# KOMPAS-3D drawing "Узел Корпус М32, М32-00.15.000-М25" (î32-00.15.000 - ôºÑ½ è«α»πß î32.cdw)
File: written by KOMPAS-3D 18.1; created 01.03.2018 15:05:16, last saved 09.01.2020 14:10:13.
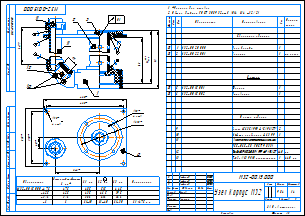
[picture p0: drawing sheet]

Sheet 1: A3, landscape

Document properties: Масса: 9.83678; Полное имя файла: М32-00.15.000 - Узел Корпус М32.a3d

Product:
- Part/product: Узел Корпус М32  | designation М32-00.15.000-М25  | pos. 0
    Масса: 9.06193
    Раздел спецификации: Сборочные единицы
    Форматы листов документа: A3
  - Component [detail]: Колено 90 @2~63 ф.FV Plast  | pos. 9  | Масса: 0.37; Раздел спецификации: Прочие изделия; source file: ..\..\..\..\1 ПКИ 3D\Полипропиленовые фитинги, трубы\Колено 90 ф63 ф.FV Plast.m3d
  - Component [detail]: Фланец  | designation М32-00.15.001  | pos. 5  | Материал: Полипропилен  ГОСТ 26996-86 (density 900 kg/m3); Масса: 0.816359; Раздел спецификации: Детали; Форматы листов документа: A3; source file: М32-00.15.001 - Фланец.m3d
  - Component [assembly]: Корпус  | designation М32-00.20.000  | pos. 1  | Материал: Полипропилен  ГОСТ 26996-86 (density 900 kg/m3); Масса: 2.99454; Раздел спецификации: Сборочные единицы; Форматы листов документа: A3; source file: ..\М32-00.20.000 - Корпус.a3d, ..\М32-00.20.000 - Корпус.cdw
  - Component [assembly]: Колонна  | designation М32-00.22.000  | pos. 2  | Масса: 0.990487; Раздел спецификации: Сборочные единицы; Форматы листов документа: A3; Примечание: см. заказ; source file: М32-00.22.000 - Колонна.a3d, М32-00.22.000 - Колонна.cdw
  - Component [detail]: Труба 63 PN10 S=5,8 FV PPR ф. FV PLAST  | pos. 11  | Материал: Полипропилен  ГОСТ 26996-86 (density 900 kg/m3); Масса: 0.152669; Раздел спецификации: Прочие изделия; Примечание: мм
  - Component [detail]: Основание  | designation М32-00.15.002-М25  | pos. 6  | Материал: Полипропилен  ГОСТ 26996-86 (density 900 kg/m3); Масса: 1.82071; Раздел спецификации: Детали; Форматы листов документа: A3
  - Component [assembly]: Муфта разборная ф63 РР  | pos. 10  | Масса: 1.69089; Раздел спецификации: Прочие изделия
- Part/product: Узел Корпус М32  | designation М32-00.15.000  | pos. 0
    Масса: 9.83678
    Раздел спецификации: Сборочные единицы
    Форматы листов документа: A3
    source file: М32-00.15.000 - Корпус М32.cdw
  - Component: Труба @2~63 PN10 полипропилен  | pos. 13  | Раздел спецификации: Прочие изделия; Примечание: 440 мм
  - Component [assembly]: Муфта разборная ф63 РР  | pos. 10  | Масса: 1.69089; Раздел спецификации: Прочие изделия; Зона: 2A
  - Component [detail]: Основание  | designation М32-00.15.002  | pos. 6
      Материал: Полипропилен  ГОСТ 26996-86 (density 900 kg/m3)
      Масса: 2.27958
      Раздел спецификации: Детали
      Форматы листов документа: A3
      Зона: 2A
      source file: М32-00.15.002 - Основание.cdw, М32-00.15.002 - Основание.m3d, М32-00.15.002-М25 - Основание.cdw
  - Component [detail]: Колено 45 63 FV PPR ф. "FV PLAST"  | pos. 9  | Материал: Полипропилен  ГОСТ 26996-86 (density 900 kg/m3); Масса: 0.34448; Раздел спецификации: Прочие изделия
  - Component [detail]: Труба 63 PN10 S=5,8 FV PPR ф. FV PLAST  | pos. 14  | Материал: Полипропилен  ГОСТ 26996-86; Масса: 0.0514; Раздел спецификации: Прочие изделия; Примечание: м
  - Component [detail]: Колено 45 63 FV PPR ф. "FV PLAST"  | pos. 9  | Материал: Полипропилен  ГОСТ 26996-86 (density 900 kg/m3); Масса: 0.34448; Раздел спецификации: Прочие изделия; Зона: 2A
  - Component [detail]: Труба 63 PN10 S=5,8 FV PPR ф. FV PLAST  | pos. 12  | Материал: Полипропилен  ГОСТ 26996-86 (density 900 kg/m3); Масса: 0.294541; Раздел спецификации: Прочие изделия; Примечание: мм; Зона: 2A
  - Component [detail]: Колонна  | designation М32-00.22.001  | pos. 2
      Масса: 0.990487
      Раздел спецификации: Сборочные единицы
      Форматы листов документа: A3
      Примечание: см. заказ
      Зона: 2A
      source file: М32-00.22.000 - Колонна.cdw, М32-00.22.001 - Колонна.m3d
  - Component [assembly]: Узел Корпус  | designation М32-00.20.000  | pos. 1
      Материал: Полипропилен  ГОСТ 26996-86 (density 900 kg/m3)
      Масса: 2.99454
      Раздел спецификации: Сборочные единицы
      Форматы листов документа: A3
      Зона: 2A
      source file: М32-00.20.000 - Корпус.cdw, М32-00.20.000 - Узел Корпус.a3d
  - Component [detail]: Фланец  | designation М32-00.15.001  | pos. 5
      Материал: Полипропилен  ГОСТ 26996-86 (density 900 kg/m3)
      Масса: 0.816359
      Раздел спецификации: Детали
      Форматы листов документа: A3
      Зона: 2A
      source file: М32-00.15.001 - Фланец.cdw, М32-00.15.001 - Фланец.m3d
  - Component: (в комплекте с уплотнительным кольцом / 055-065-58 ГОСТ 9833)  | pos. 11  | Раздел спецификации: Прочие изделия
- Part/product: Корпус М32 с косячным корпусом М40  | designation М32-00.15.000-666  | pos. 0
    Масса: 9.75067
    Раздел спецификации: Сборочные единицы
    Форматы листов документа: A3
  - Component [detail]: Труба 63 PN10 S=5,8 FV PPR ф. FV PLAST  | designation 1001  | pos. 11  | Материал: Полипропилен  ГОСТ 26996-86 (density 900 kg/m3); Масса: 0.324558; Раздел спецификации: Прочие изделия; Примечание: мм
  - Component [detail]: Колено 45@1~ @2~63 FV PPR ф. "FV PLAST"  | qty 2  | pos. 10  | Материал: Полипропилен  ГОСТ 26996-86 (density 900 kg/m3); Масса: 0.34448; Раздел спецификации: Прочие изделия
  - Component [detail]: Труба 63 PN10 S=5,8 FV PPR ф. FV PLAST  | designation М32колено  | pos. 0  | Материал: Полипропилен  ГОСТ 26996-86 (density 900 kg/m3); Масса: 0.051404; Раздел спецификации: Прочие изделия; Примечание: м
  - Component [assembly]: Муфта разборная ф63 РР  | pos. 11  | Масса: 1.69089; Раздел спецификации: Прочие изделия
  - Component [assembly]: Корпус косячный ММ32  | designation М40-00.30.000-666  | pos. 17  | Материал: Полипропилен  ГОСТ 26996-86 (density 900 kg/m3); Масса: 2.90843; Раздел спецификации: Сборочные единицы; source file: ..\..\Магна ins 40\3Д\М40-00.30.000 - Корпус.a3d

Title block, sheet 1: Наименование: Узел Корпус М32; designation: М32-00.15.000; Масса: 9,84; scale: 1:4; Количество листов документа: 1; organisation: ЗАО «Астерион»; Форматы листов документа: A3; stored path: Z:\Магна\Магна Ins\Магна ins 32\М32-00.15.000 - Корпус М32.cdw; Разработал: Милов; Т. контр.: Лучихин

Views: Вид 1, Местный разрез 1, Местный разрез 2, Местный разрез 3, Спереди, Проекционный вид 2, Вид:1, Вид:2, Вид:3
Referenced files in D:\Magna\Магна Ins\Магна ins 32\Для Караби\: М32-00.15.000 - Узел Корпус М32.a3d, М40-00.30.001 - Штифт 10.m3d, М32-00.15.001 - Фланец.m3d, М32-00.15.001 - Фланец.cdw, М32-00.20.000 - Узел Корпус.a3d, М32-00.20.000 - Корпус.cdw, М32-00.22.001 - Колонна.m3d, М32-00.22.000 - Колонна.cdw, М32-00.15.002 - Основание.m3d, М32-00.15.002 - Основание.cdw, М32-00.15.002-М25 - Основание.cdw, М32-00.21.000 - Узел Кольцо.a3d, М32-00.21.001 - Кольцо.m3d, М32-00.20.002 - Корпус.m3d, Труба 63 PN10 S=5,8 FV PPR ф. FV PLAST.m3d, Колено 45гр 63 FV PPR ф. FV PLAST.m3d, Фланец МР ф63 РР.m3d, Фланец прижимной МР ф63 РР.m3d, Гайка МР ф63 РР.m3d, Муфта разборная ф63 РР.a3d
Referenced files in Z:\Магна\Магна Ins\Магна ins 32\: М32-00.15.000 - Корпус М32.a3d, М32-00.20.002 - Корпус.m3d, М32-00.20.001 - Стопор.m3d, М32-00.20.003 - Крышка.m3d, М32-00.22.002 - Отбойник.m3d
Referenced files in D:\1 ПКИ 3D\Полипропиленовые фитинги, трубы\Трубы\: Труба 63 PN10 S=5,8 FV PPR ф. FV PLAST.m3d
Referenced files in \\192.168.87.28\Konstructor_doc\Магна\Магна Ins\Магна ins 32\: М32-00.21.001 - Кольцо.m3d
Referenced files in Z:\1 ПКИ 3D\Полипропиленовые фитинги, трубы\Трубы\: Труба 63 PN10 S=5,8 FV PPR ф. FV PLAST.m3d
Referenced files in Z:\1 ПКИ 3D\Полипропиленовые фитинги, трубы\Разборные муфты\: Фланец прижимной МР ф63 РР.m3d, Фланец МР ф63 РР.m3d, Гайка МР ф63 РР.m3d
Referenced files in Z:\1 ПКИ 3D\Полипропиленовые фитинги, трубы\: Колено 45гр 63 FV PPR ф. FV PLAST.m3d
Referenced files in \\192.168.87.28\Konstructor_doc\1 ПКИ 3D\Полипропиленовые фитинги, трубы\Трубы\: Труба 63 PN10 S=5,8 FV PPR ф. FV PLAST.m3d
Referenced files in D:\Magna\Магна Ins\Магна ins 32\: М32-00.20.002 - Корпус.m3d
Referenced files in D:\1 ПКИ 3D\Полипропиленовые фитинги, трубы\Разборные муфты\: Фланец прижимной МР ф63 РР.m3d, Фланец МР ф63 РР.m3d
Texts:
  Длина погружной части
  L, мм*
  L1, мм
  L2, мм
  L3, мм
  L1 475 мм
  Фланец
  Узел Корпус
  Колонна
  см. заказ
  Труба 63 PN10 S=5,8 FV PPR ф. FV PLAST
  Колено 45 63 FV PPR ф. "FV PLAST"
  Основание
  Муфта разборная ф63 РР
  (в комплекте с уплотнительным кольцом
  (в комплекте с уплотнительным кольцом / 055-065-58 ГОСТ 9833)
  Труба  63 PN10 полипропилен
  Труба @2~63 PN10 полипропилен
  Лифлянд
  Кольцо
  Узел Кольцо
  Корпус
  Штифт 10
  Фланец МР ф63 РР
  Фланец прижимной МР ф63 РР
  Гайка МР ф63 РР
Dimensions and other numbers on the sheet: 475; 485; 515; 445; -425; -375; 425; 375; 435; 465; 395; 385; 415; 345; 0.1; 55; 1; 2; 5; 10; 11; 12; 246; 60; 290; 325; 460; 215; 15; 4 отв.; 6; 4; 440; 9; 055-065-58 ГОСТ 9833); 13; 440 мм; 1:4; 9,84; 01.07.2019; 12.07.2019; 3; 31.10.2019

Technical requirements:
  *Размеры для справок.
  Общие допуски ГОСТ 30893.2-тК (H14, h14,  t2/2).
